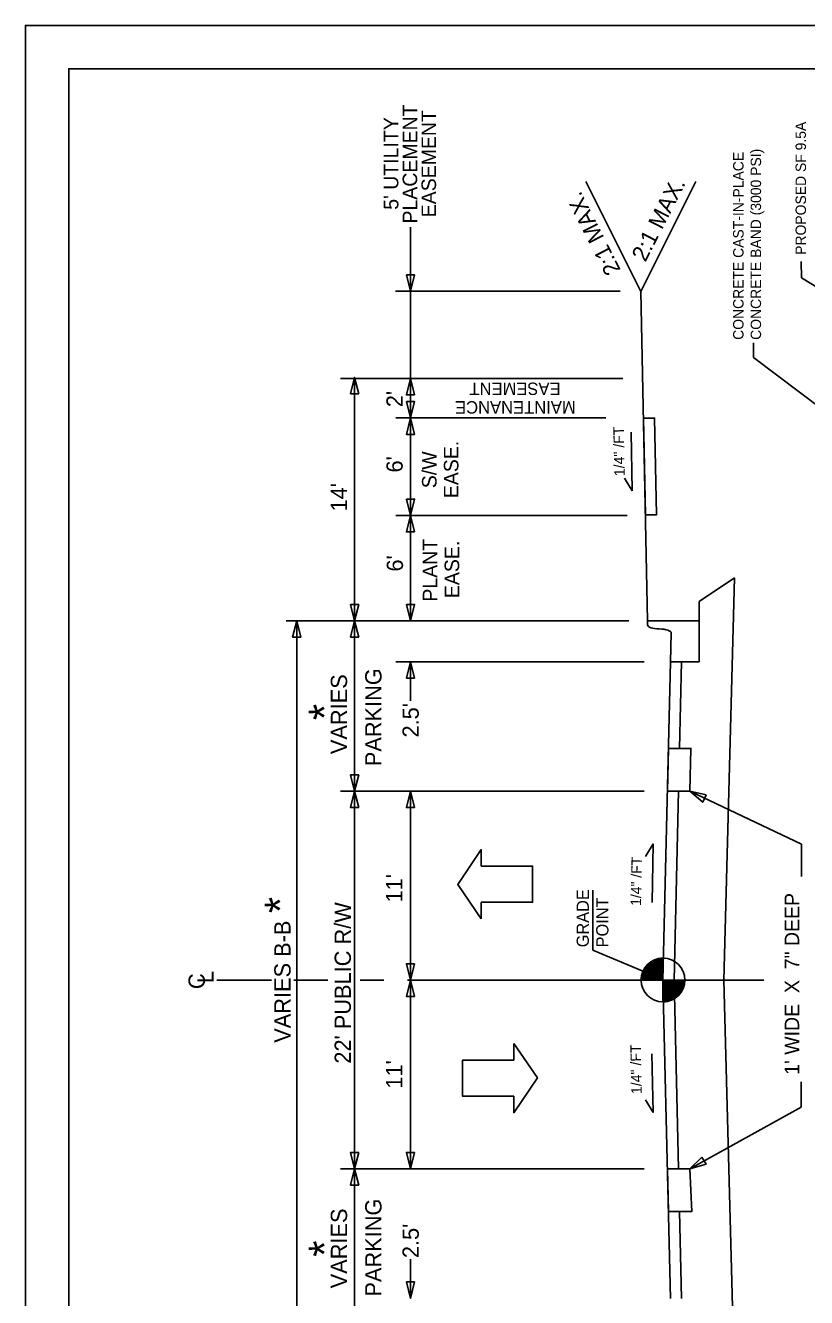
# Model space of a CAD drawing. Extents: x 0 to 8.5, y 0 to 11.
# Drawn here: x 0 to 4.5, y 3.67 to 11 of the extents above; entities that cross this region are included whole.
import ezdxf

# ---------------------------------------------------------------- set-up
doc = ezdxf.new("R2010")
doc.units = 0
for name, color, linetype in [('DTL-TEXT', 7, 'Continuous'), ('Old_Level_1', 7, 'Continuous'), ('Old_Level_11', 7, 'Continuous'), ('Old_Level_5', 7, 'Continuous'), ('PROP LANE ARROW CELL', 7, 'Continuous'), ('Prop Shade Light', 7, 'Continuous'), ('SHEET BORDER', 7, 'Continuous'), ('SHEET TRIM BORDER', 7, 'Continuous'), ('Typical Grade Point Symbol CELL', 7, 'Continuous'), ('Typical Pavement Slope Information CELL', 7, 'Continuous')]:
    doc.layers.add(name, color=color, linetype=linetype)

msp = doc.modelspace()

# ---------------------------------------------------------------- linework, layer by layer
at = {"layer": 'DTL-TEXT'}
for q in [(4.4719, 9.6397), (4.8601, 9.3082)]:
    msp.add_line((4.474, 9.5455), q, dxfattribs=at)
msp.add_lwpolyline([(4.86, 8.5858), (4.1976, 9.0867), (4.1976, 9.1701)], dxfattribs=at)
at = {"layer": 'Old_Level_1'}
for p, q in [((3.2306, 10.1014), (3.5476, 9.4673)), ((3.8647, 10.1014), (3.5476, 9.4673)), ((3.5871, 7.5689), (3.5476, 9.4673)), ((3.8834, 7.6796), (4.0884, 7.8163)), ((3.8834, 7.5689), (3.8834, 7.6796)), ((3.8834, 7.5689), (3.5871, 7.5689)), ((3.5871, 7.5453), (3.5871, 7.5689)), ((3.8834, 7.5689), (3.8834, 7.6161)), ((3.8834, 7.333), (3.8834, 7.5689)), ((3.7233, 7.4979), (3.7181, 7.333)), ((3.7181, 7.333), (3.6756, 5.4982)), ((3.8834, 7.333), (3.7181, 7.333)), ((3.7829, 7.333), (3.7713, 6.8332)), ((3.7656, 6.5861), (3.7404, 5.4983)), ((3.7184, 3.6635), (3.6756, 5.4982)), ((3.7657, 4.4112), (3.7404, 5.4983)), ((3.7832, 3.6635), (3.7715, 4.1638))]:
    msp.add_line(p, q, dxfattribs=at)
msp.add_lwpolyline([(4.0884, 3.1802), (4.0263, 5.4981), (4.0884, 7.8163)], dxfattribs=at)
for centre, major_axis, ratio, start_param, end_param in [((3.6577, 7.5453), (0.0708, 0), 0.333333, 3.141581, 4.664257), ((3.6509, 7.4982), (0.0724, 0), 0.32599, 6.272817, 7.805849)]:
    msp.add_ellipse(centre, major_axis=major_axis, ratio=ratio, start_param=start_param, end_param=end_param, dxfattribs=at)
at = {"layer": 'Old_Level_11'}
for p, q in [((2.2201, 9.8374), (2.2201, 9.4677)), ((2.1326, 9.4677), (3.4292, 9.4677)), ((2.2201, 9.4677), (2.2201, 8.7376)), ((1.8159, 8.9653), (3.4444, 8.9654)), ((1.8978, 8.9653), (1.8977, 6.5863)), ((2.1361, 8.7376), (3.3461, 8.7376)), ((2.2201, 8.7376), (2.22, 8.2684)), ((2.2201, 8.7376), (2.22, 8.2684)), ((2.2201, 8.2683), (2.22, 7.5689)), ((2.1361, 8.1755), (3.4681, 8.1756)), ((1.5037, 7.5688), (3.4789, 7.5689)), ((1.5639, 3.4277), (1.5638, 7.5688)), ((2.136, 7.3329), (3.5673, 7.333)), ((2.22, 7.3329), (2.22, 7.1071)), ((1.816, 6.5863), (3.5673, 6.5863)), ((1.8979, 4.4102), (1.8979, 6.5863)), ((2.2199, 5.4982), (2.2199, 6.5863)), ((3.8303, 6.5861), (4.4743, 6.2818)), ((4.4743, 6.0943), (4.4743, 6.2818)), ((3.271, 6.0162), (3.271, 5.6703)), ((3.271, 5.6703), (3.6746, 5.5006)), ((1.4189, 5.4982), (1.1033, 5.4982)), ((1.7425, 5.4982), (1.5477, 5.4982)), ((2.0654, 5.4982), (1.9295, 5.4982)), ((4.2562, 5.4982), (2.2027, 5.4982)), ((2.2199, 5.4982), (2.2199, 4.4102)), ((4.4718, 4.7664), (4.4718, 4.9123)), ((3.8303, 4.4104), (4.4718, 4.7664)), ((1.816, 4.4102), (3.5673, 4.4102)), ((1.8978, 2.0312), (1.8977, 4.4102)), ((2.22, 3.6636), (2.22, 3.8894))]:
    msp.add_line(p, q, dxfattribs=at)
for points in [[(2.1965, 9.562), (2.2201, 9.4677), (2.2437, 9.562)], [(1.9214, 8.8768), (1.8978, 8.9712), (1.8742, 8.8768)], [(2.2437, 8.871), (2.2201, 8.9654), (2.1965, 8.871)], [(2.2437, 8.871), (2.2201, 8.9654), (2.1965, 8.871)], [(2.1965, 8.8319), (2.2201, 8.7376), (2.2437, 8.8319)], [(2.1965, 8.8319), (2.2201, 8.7376), (2.2437, 8.8319)], [(2.2437, 8.6432), (2.2201, 8.7376), (2.1965, 8.6432)], [(2.2437, 8.6432), (2.2201, 8.7376), (2.1965, 8.6432)], [(2.1965, 8.27), (2.22, 8.1756), (2.2436, 8.27)], [(2.1965, 8.27), (2.22, 8.1756), (2.2436, 8.2699)], [(2.2436, 8.0812), (2.22, 8.1756), (2.1965, 8.0812)], [(2.2436, 8.0812), (2.22, 8.1756), (2.1965, 8.0812)], [(1.8742, 7.6632), (1.8978, 7.5688), (1.9214, 7.6632)], [(2.1964, 7.6633), (2.22, 7.5689), (2.2436, 7.6633)], [(2.1964, 7.6633), (2.22, 7.5689), (2.2436, 7.6633)], [(1.5874, 7.4745), (1.5638, 7.5688), (1.5402, 7.4745)], [(1.5874, 7.4745), (1.5638, 7.5688), (1.5402, 7.4745)], [(1.9214, 7.4745), (1.8978, 7.5688), (1.8742, 7.4745)], [(2.2436, 7.2385), (2.22, 7.3329), (2.1964, 7.2385)], [(1.8741, 6.6807), (1.8977, 6.5863), (1.9213, 6.6807)], [(1.9215, 6.4919), (1.8979, 6.5863), (1.8743, 6.4919)], [(1.9215, 6.4919), (1.8979, 6.5863), (1.8743, 6.4919)], [(2.2436, 6.4919), (2.22, 6.5863), (2.1964, 6.4919)], [(2.2436, 6.4919), (2.22, 6.5863), (2.1964, 6.4919)], [(3.9254, 6.5656), (3.8303, 6.5861), (3.9046, 6.5233)], [(2.2435, 5.5926), (2.2199, 5.4982), (2.1963, 5.5926)], [(2.2435, 5.5926), (2.2199, 5.4982), (2.1963, 5.5926)], [(2.2435, 5.4039), (2.2199, 5.4982), (2.1963, 5.4039)], [(1.9215, 4.5046), (1.8979, 4.4102), (1.8743, 4.5046)], [(2.2436, 4.5046), (2.22, 4.4102), (2.1964, 4.5046)], [(3.9003, 4.478), (3.8303, 4.4104), (3.9238, 4.4371)], [(1.8741, 4.3158), (1.8977, 4.4102), (1.9213, 4.3158)], [(2.2436, 3.758), (2.22, 3.6636), (2.1964, 3.758)]]:
    msp.add_lwpolyline(points, close=True, dxfattribs=at)
at = {"layer": 'Old_Level_5'}
for points in [[(3.5869, 7.5453), (3.5871, 7.5689), (3.8834, 7.5689), (3.8834, 7.333), (3.7186, 7.333)], [(3.6544, 7.5217), (3.6543, 7.5217)], [(3.7186, 7.333), (3.7181, 7.333), (3.7233, 7.4979)]]:
    msp.add_lwpolyline(points, dxfattribs=at)
for centre, major_axis, ratio, start_param, end_param in [((3.6577, 7.5453), (0.0708, 0), 0.333333, 3.141581, 4.664257), ((3.6509, 7.4982), (0.0724, 0), 0.32599, 6.272817, 7.805849)]:
    msp.add_ellipse(centre, major_axis=major_axis, ratio=ratio, start_param=start_param, end_param=end_param, dxfattribs=at)
at = {"layer": 'PROP LANE ARROW CELL'}
for points in [[(2.6282, 5.8515), (2.6282, 5.9465), (2.9238, 5.9465), (2.9238, 6.1555), (2.6282, 6.1555), (2.6282, 6.2506), (2.4921, 6.049), (2.6282, 5.8515)], [(2.8156, 5.1325), (2.8156, 5.0374), (2.5199, 5.0374), (2.5199, 4.8284), (2.8156, 4.8284), (2.8156, 4.7334), (2.9517, 4.9349), (2.8156, 5.1325)]]:
    msp.add_lwpolyline(points, dxfattribs=at)
at = {"layer": 'Prop Shade Light'}
for points in [[(3.5744, 8.1786), (3.5628, 8.7374), (3.6267, 8.7374), (3.6375, 8.1786)], [(3.5744, 8.1786), (3.5628, 8.7374), (3.6267, 8.7374), (3.6375, 8.1786)], [(3.7008, 6.5861), (3.7065, 6.8329), (3.8362, 6.8336), (3.8303, 6.5861)], [(3.7008, 4.4103), (3.7065, 4.1636), (3.8418, 4.1634), (3.8303, 4.4104)]]:
    msp.add_lwpolyline(points, close=True, dxfattribs=at)
at = {"layer": 'SHEET BORDER'}
msp.add_lwpolyline([(8.25, 10.75), (0.25, 10.75), (0.25, 0.25), (8.25, 0.25)], close=True, dxfattribs=at)
at = {"layer": 'SHEET TRIM BORDER'}
msp.add_lwpolyline([(8.5, 11), (0, 11), (0, 0), (8.5, 0)], close=True, dxfattribs=at)
at = {"layer": 'Typical Grade Point Symbol CELL'}
for p, q in [((3.6756, 5.6243), (3.6756, 5.4982)), ((3.6756, 5.4982), (3.5495, 5.4983)), ((3.8016, 5.498), (3.6756, 5.4982)), ((3.6756, 5.3722), (3.6756, 5.4982)), ((3.6756, 5.4982), (3.8016, 5.498))]:
    msp.add_line(p, q, dxfattribs=at)
for points in [[(3.5739, 5.5725), (3.6756, 5.5725)], [(3.5756, 5.575), (3.6756, 5.575)], [(3.5775, 5.5775), (3.6756, 5.5775)], [(3.5798, 5.58), (3.6756, 5.58)], [(3.582, 5.5825), (3.6756, 5.5825)], [(3.5843, 5.5851), (3.6756, 5.5851)], [(3.5868, 5.5876), (3.6756, 5.5876)], [(3.5893, 5.5901), (3.6756, 5.5901)], [(3.5921, 5.5926), (3.6756, 5.5926)], [(3.5952, 5.5952), (3.6756, 5.5951)], [(3.5983, 5.5977), (3.6756, 5.5977)], [(3.6016, 5.6002), (3.6756, 5.6002)], [(3.6053, 5.6027), (3.6756, 5.6027)], [(3.6092, 5.6052), (3.6756, 5.6052)], [(3.6134, 5.6077), (3.6756, 5.6077)], [(3.6179, 5.6103), (3.6756, 5.6103)], [(3.6232, 5.6128), (3.6756, 5.6128)], [(3.6291, 5.6153), (3.6756, 5.6153)], [(3.6361, 5.6178), (3.6756, 5.6178)], [(3.6448, 5.6204), (3.6756, 5.6204)], [(3.6576, 5.6229), (3.6756, 5.6229)], [(3.5495, 5.5019), (3.6756, 5.5019)], [(3.5495, 5.4994), (3.5495, 5.4994), (3.6756, 5.4994)], [(3.5498, 5.5069), (3.6756, 5.5069)], [(3.5498, 5.5044), (3.6756, 5.5044)], [(3.5501, 5.5095), (3.6756, 5.5094)], [(3.5504, 5.512), (3.6756, 5.512)], [(3.5507, 5.5145), (3.6756, 5.5145)], [(3.5509, 5.517), (3.6756, 5.517)], [(3.5512, 5.5195), (3.6756, 5.5195)], [(3.5518, 5.5221), (3.6756, 5.5221)], [(3.5523, 5.5246), (3.6756, 5.5246)], [(3.5529, 5.5271), (3.6756, 5.5271)], [(3.5535, 5.5296), (3.6756, 5.5296)], [(3.5543, 5.5321), (3.6756, 5.5321)], [(3.5549, 5.5347), (3.6756, 5.5347)], [(3.5557, 5.5372), (3.6756, 5.5372)], [(3.5565, 5.5397), (3.6756, 5.5397)], [(3.5574, 5.5422), (3.6756, 5.5422)], [(3.5585, 5.5447), (3.6756, 5.5447)], [(3.5596, 5.5473), (3.6756, 5.5473)], [(3.5607, 5.5498), (3.6756, 5.5498)], [(3.5619, 5.5523), (3.6756, 5.5523)], [(3.563, 5.5548), (3.6756, 5.5548)], [(3.5644, 5.5573), (3.6756, 5.5573)], [(3.5658, 5.5599), (3.6756, 5.5599)], [(3.5672, 5.5624), (3.6756, 5.5624)], [(3.5686, 5.5649), (3.6756, 5.5649)], [(3.5703, 5.5674), (3.6756, 5.5674)], [(3.5719, 5.5699), (3.6756, 5.5699)], [(3.6756, 5.4963), (3.8016, 5.4963), (3.8016, 5.4963)], [(3.6756, 5.4938), (3.8016, 5.4938)], [(3.6756, 5.4913), (3.8013, 5.4912)], [(3.6756, 5.4887), (3.8013, 5.4887)], [(3.6756, 5.4862), (3.801, 5.4862)], [(3.6756, 5.4837), (3.8007, 5.4837)], [(3.6756, 5.4812), (3.8004, 5.4812)], [(3.6756, 5.4786), (3.7999, 5.4786)], [(3.6756, 5.4761), (3.7996, 5.4761)], [(3.6756, 5.4736), (3.7991, 5.4736)], [(3.6756, 5.4711), (3.7985, 5.4711)], [(3.6756, 5.4686), (3.7979, 5.4686)], [(3.6756, 5.466), (3.7974, 5.466)], [(3.6756, 5.4635), (3.7965, 5.4635)], [(3.6756, 5.461), (3.796, 5.461)], [(3.6756, 5.4585), (3.7951, 5.4585)], [(3.6756, 5.456), (3.7943, 5.456)], [(3.6756, 5.4534), (3.7935, 5.4534)], [(3.6756, 5.4509), (3.7923, 5.4509)], [(3.6756, 5.4484), (3.7912, 5.4484)], [(3.6756, 5.4459), (3.7901, 5.4459)], [(3.6756, 5.4434), (3.789, 5.4434)], [(3.6756, 5.4408), (3.7879, 5.4408)], [(3.6756, 5.4383), (3.7864, 5.4383)], [(3.6756, 5.4358), (3.7851, 5.4358)], [(3.6756, 5.4333), (3.7836, 5.4333)], [(3.6756, 5.4308), (3.782, 5.4308)], [(3.6756, 5.4282), (3.7803, 5.4282)], [(3.6756, 5.4257), (3.7786, 5.4257)], [(3.6756, 5.4232), (3.7769, 5.4232)], [(3.6756, 5.4207), (3.775, 5.4207)], [(3.6756, 5.4182), (3.773, 5.4182)], [(3.6756, 5.4156), (3.7708, 5.4156)], [(3.6756, 5.4131), (3.7685, 5.4131)], [(3.6756, 5.4106), (3.7663, 5.4106)], [(3.6756, 5.4081), (3.7638, 5.4081)], [(3.6756, 5.4056), (3.761, 5.4056)], [(3.6756, 5.403), (3.7582, 5.403)], [(3.6756, 5.4005), (3.7551, 5.4005)], [(3.6756, 5.398), (3.752, 5.398)], [(3.6756, 5.3955), (3.7486, 5.3955)], [(3.6756, 5.393), (3.745, 5.393)], [(3.6756, 5.3904), (3.7411, 5.3904)], [(3.6756, 5.3879), (3.7366, 5.3879)], [(3.6756, 5.3854), (3.7318, 5.3854)], [(3.6756, 5.3829), (3.7265, 5.3829)], [(3.6756, 5.3804), (3.7206, 5.3803)], [(3.6756, 5.3778), (3.7131, 5.3778)], [(3.6756, 5.3753), (3.7041, 5.3753)], [(3.6756, 5.3728), (3.6893, 5.3728)]]:
    msp.add_lwpolyline(points, dxfattribs=at)
msp.add_circle((3.6755, 5.4981), 0.126, dxfattribs=at)
for start, end in [(89.98837, 179.98837), (269.98837, 359.98837)]:
    msp.add_arc((3.6755, 5.4981), 0.126, start, end, dxfattribs=at)
at = {"layer": 'Typical Pavement Slope Information CELL'}
for p, q in [((3.4985, 8.3181), (3.4918, 8.6563)), ((3.4985, 8.3181), (3.4541, 8.3915)), ((3.6193, 6.2834), (3.5749, 6.2099)), ((3.6193, 6.2834), (3.6125, 5.9451)), ((3.6182, 4.7339), (3.6114, 5.0721)), ((3.6182, 4.7339), (3.5738, 4.8073))]:
    msp.add_line(p, q, dxfattribs=at)

# ---------------------------------------------------------------- texts
at = {"layer": 'DTL-TEXT'}
for s, p in [('PROPOSED SF 9.5A', (4.4999, 9.678)), ('CONCRETE CAST-IN-PLACE', (4.1399, 9.1879)), ('CONCRETE BAND (3000 PSI)', (4.241, 9.1879))]:
    msp.add_text(s, height=0.06, rotation=90, dxfattribs=at).set_placement(p)
at = {"layer": 'Old_Level_11'}
for s, height, rotation, p in [('PLACEMENT', 0.084, 90, (2.2587, 9.8583)), ('EASEMENT', 0.084, 90, (2.3674, 9.8942)), ("5' UTILITY", 0.084, 90, (2.1499, 9.9377)), ('2:1 MAX.', 0.09385, 62.953, (3.5741, 9.6323)), ('2:1 MAX.', 0.09385, 117.047, (3.4338, 9.59)), ("2'", 0.09385, 89.99789, (2.1748, 8.7998)), ("2'", 0.09385, 89.99789, (2.1748, 8.7998)), ('EASEMENT', 0.0714, 180, (3.085, 8.9417)), ('MAINTENANCE', 0.0714, 180, (3.172, 8.8346)), ('EASE.', 0.084, 90, (2.4963, 8.2754)), ("6'", 0.09385, 89.99789, (2.1748, 8.4233)), ("6'", 0.09385, 89.99789, (2.1748, 8.4233)), ('S/W', 0.084, 90, (2.3703, 8.333)), ("14'", 0.09385, 90, (1.8545, 8.1988)), ('PLANT', 0.084, 90, (2.3746, 7.6792)), ('EASE.', 0.084, 90, (2.5006, 7.6994)), ("6'", 0.09385, 89.99789, (2.1767, 7.8524)), ("6'", 0.09385, 89.99789, (2.1767, 7.8524)), ('PARKING', 0.09385, 90, (2.0527, 6.7306)), ('VARIES', 0.09385, 89.99789, (1.8544, 6.8003)), ('*', 0.18, 90.00211, (1.8138, 6.9962)), ("2.5'", 0.09385, 89.99789, (2.2678, 6.8961)), ("11'", 0.09385, 90.00211, (2.1725, 5.9452)), ('GRADE', 0.07039, 89.99789, (3.2482, 5.687)), ('*', 0.18, 89.99789, (1.5585, 5.8838)), ("22' PUBLIC R/W", 0.093852, 90.00211, (1.8763, 5.0163)), ('POINT', 0.07039, 89.99789, (3.361, 5.6865)), ('1\' WIDE  X  7" DEEP', 0.084, 90, (4.4608, 4.9524)), ('VARIES B-B', 0.09385, 90.00211, (1.5287, 5.1366)), ('C', 0.0944, 89.99789, (1.0346, 5.446)), ('L', 0.0944, 89.94479, (1.0847, 5.4798)), ("11'", 0.09385, 89.99789, (2.1725, 4.8724)), ('PARKING', 0.09385, 90, (2.0527, 3.6737)), ('VARIES', 0.09385, 90.00211, (1.8544, 3.7214)), ("2.5'", 0.09385, 90.00211, (2.2679, 3.8956)), ('*', 0.18, 89.99789, (1.8138, 3.9035))]:
    msp.add_text(s, height=height, rotation=rotation, dxfattribs=at).set_placement(p)
at = {"layer": 'Typical Pavement Slope Information CELL'}
for height, rotation, p in [(0.06078, 91.14785, (3.4554, 8.4027)), (0.06, 88.85215, (3.5488, 5.9252)), (0.06078, 91.14785, (3.5536, 4.8416))]:
    msp.add_text('1/4" /FT', height=height, rotation=rotation, dxfattribs=at).set_placement(p)

doc.saveas('drawing.dxf')
